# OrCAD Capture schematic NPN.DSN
size A
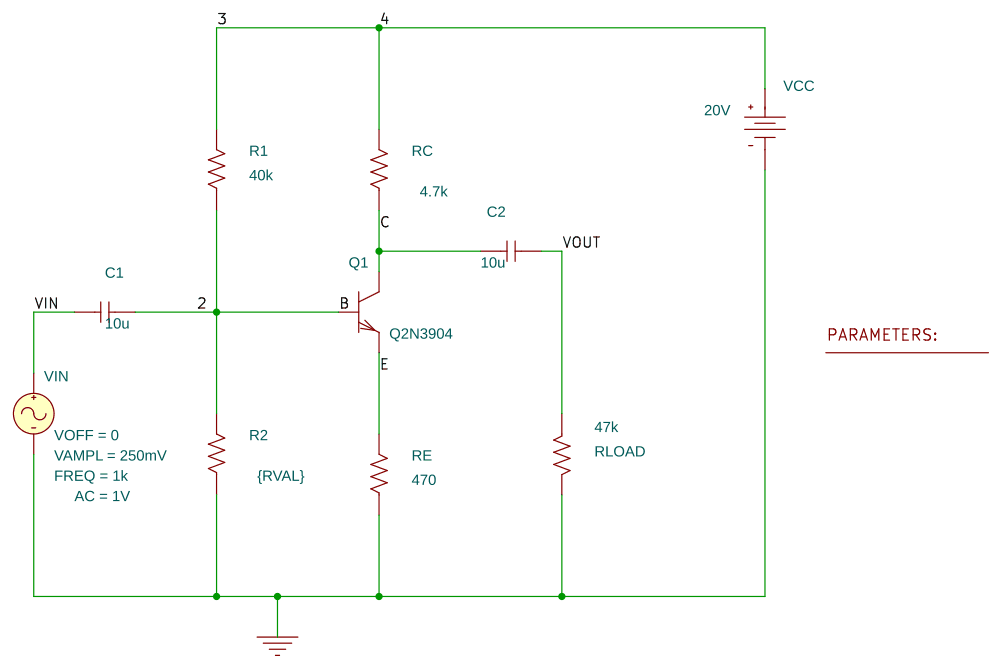
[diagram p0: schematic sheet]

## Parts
1  PARAM
C1  10u  [RAD/CK05]
C2  10u  [RAD/CK05]
Q1  Q2N3904  [TO92]
R1  40k  [AX/RC05]
R2  {RVAL}  [AX/RC05]
RC  4.7k  [AX/RC05]
RE  470  [AX/RC05]
RLOAD  47k  [AX/RC05]
VCC  VDC
VIN  VSIN

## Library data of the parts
1 = PARAM: RVAL: 3.5k
C1 C2 = C
Q1 = Q2N3904
R1 R2 RC RE RLOAD = R
VCC = VDC: DC: 20V
VIN = VSIN: AC: 1V; FREQ: 1k; VAMPL: 250mV; VOFF: 0

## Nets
VIN: C1.1 VIN.1(+)
0: R2.1 RE.1 RLOAD.2 VCC.1(-) VIN.2(-)
2: C1.2 Q1.2(b) R1.1 R2.2
3: R1.2 RC.2 VCC.0(+)
C: C2.2 Q1.3(c) RC.1
E: Q1.1(e) RE.2
VOUT: C2.1 RLOAD.1
